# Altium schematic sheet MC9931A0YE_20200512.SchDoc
size A3
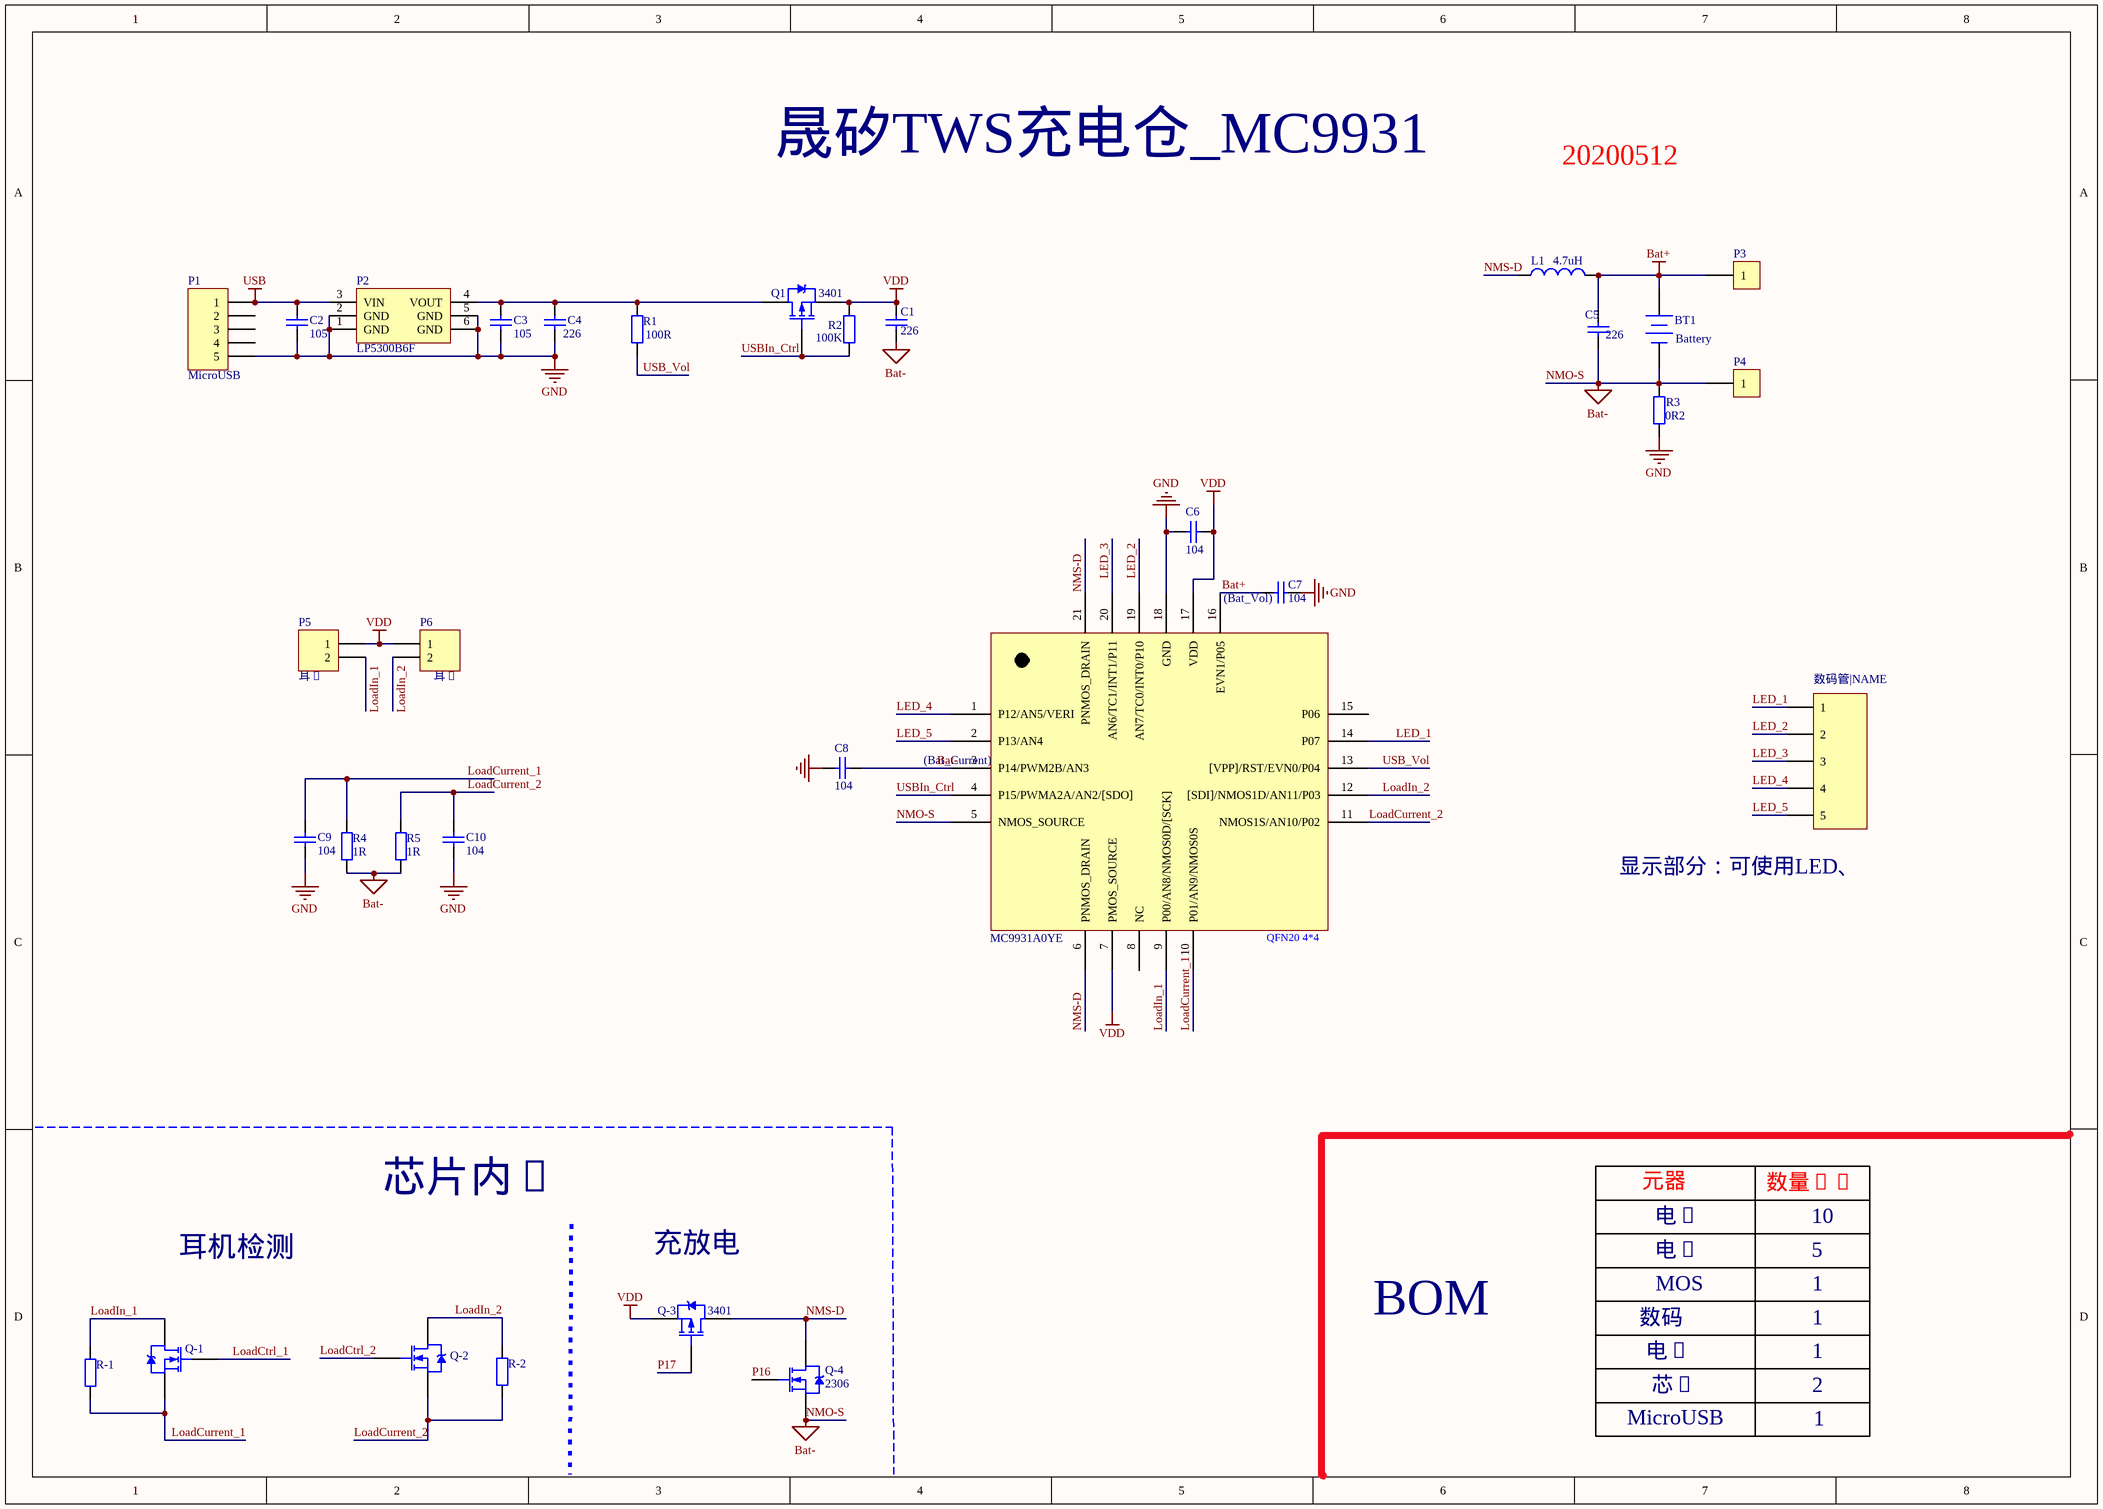
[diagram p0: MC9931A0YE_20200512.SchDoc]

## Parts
1  Header 5  [数码管_5脚]  (value not drawn)
BT1  Battery
C1  value 226  [0805]  (hidden comment: Cap)
C2  value 105  [0603]  (hidden comment: Cap)
C3  value 105  [0603]  (hidden comment: Cap)
C4  value 226  [0805]  (hidden comment: Cap)
C5  value 226  [0805]  (hidden comment: Cap)
C6  value 104  [0603]  (hidden comment: Cap)
C7  value 104  [0603]  (hidden comment: Cap)
C8  value 104  [0603]  (hidden comment: Cap)
C9  value 104  [0603]  (hidden comment: Cap)
C10  value 104  [0603]  (hidden comment: Cap)
L1  4.7uH  [电感SMD_201610]
MC1  MC9931A0YE  [QFN20_4*4 _Large]
P1  MicroUSB  [MICRO-USB_standard]
P2  LP5300B6F  [SOT23-6]
P3  Header 2  [1焊盘]  (value not drawn)
P4  Header 2  [1焊盘]  (value not drawn)
P5  Header 2  [1*2焊盘]  (value not drawn)
P6  Header 2  [1*2焊盘]  (value not drawn)
Q1  3401  [SOT-23_PMOS]
Q-1  3134  [TO-220AB]  (value not drawn)
Q-2  3134  [TO-220AB]  (value not drawn)
Q-3  3401  [SOT-23_PMOS]
Q-4  2306  [SOT-23_NMOS]
R1  value 100R  [0603]  (hidden comment: Res2)
R2  value 100K  [0603]  (hidden comment: Res2)
R3  value 0R2  [1206]  (hidden comment: Res2)
R4  value 1R  [0805]  (hidden comment: Res2)
R5  value 1R  [0805]  (hidden comment: Res2)
R-1  Res2  [AXIAL-0.4]  (value not drawn)
R-2  Res2  [AXIAL-0.4]  (value not drawn)

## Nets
Bat+: BT1.1(+) C5.2 C7.2 L1.2 MC1.16(EVN1/P05) P3.1
Bat-: BT1.2(-) C1.1 C5.1 C8.2 MC1.3(P14/PWM2B/AN3) MC1.5(NMOS_SOURCE) P4.1 Q-4.3(S) R3.2 R4.2 R5.2  [also labelled NMO-S]
GND: C2.1 C3.1 C4.1 C6.2 C7.1 C8.1 C9.2 C10.2 MC1.18(GND) P1.5 P2.1(GND) P2.2(GND) P2.5(GND) P2.6(GND) R3.1
USB: C2.2 P1.1 P2.3(VIN)
VDD: C1.2 C6.1 MC1.7(PMOS_SOURCE) MC1.17(VDD) P5.1 P6.1 Q1.3(S) Q-3.3(S) R2.1
LED_1: 1.1 MC1.14(P07)
LED_2: 1.2 MC1.19(AN7/TC0/INT0/P10)
LED_3: 1.3 MC1.20(AN6/TC1/INT1/P11)
LED_4: 1.4 MC1.1(P12/AN5/VERI)
LED_5: 1.5 MC1.2(P13/AN4)
LoadCtrl_1: Q-1.1(G)
LoadCtrl_2: Q-2.1(G)
LoadCurrent_1: C9.1 MC1.10(P01/AN9/NMOS0S) Q-1.3(S) R4.1 R-1.1
LoadCurrent_2: C10.1 MC1.11(NMOS1S/AN10/P02) Q-2.3(S) R5.1 R-2.1
LoadIn_1: MC1.9(P00/AN8/NMOS0D/[SCK]) P5.2 Q-1.2(D) R-1.2
LoadIn_2: MC1.12([SDI]/NMOS1D/AN11/P03) P6.2 Q-2.2(D) R-2.2
NMS-D: L1.1 MC1.6(PNMOS_DRAIN) MC1.21(PNMOS_DRAIN) Q-3.2(D) Q-4.2(D)
P16: Q-4.1(G)
P17: Q-3.1(G)
USB_Vol: MC1.13([VPP]/RST/EVN0/P04) R1.1
USBIn_Ctrl: MC1.4(P15/PWMA2A/AN2/[SDO]) Q1.1(G) R2.2
NetC3_2: C3.2 C4.2 P2.4(VOUT) Q1.2(D) R1.2

Not connected (* = marked no-connect by the designer): MC1 8(NC) 15(P06); P1 2 3 4

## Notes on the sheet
- 晟矽TWS充电仓_MC9931
- 20200512
- (near C7) (Bat_Vol)
- (near C8) (Bat_Current)
- 显示部分：可使用LED、
- (near MC1) QFN20 4*4
- 元器
- 数量(�
- 耳机检测
- 芯片内�
- 充放电
- 电�
- 10
- 5
- BOM
- 数码
- MOS
- 1
- 芯�
- 2
- MicroUSB

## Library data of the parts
1 P1 = Header 5: Header, 5-Pin
BT1 = Battery: Multicell Battery
C1-C10 = Cap: Capacitor
L1 = Inductor: Code_IEC: 1005; Value: 10mH
MC1 = MC9931A0ZQ
P2 = Header 3X2A: Header, 3-Pin, Dual row
P3-P6 = Header 2: Header, 2-Pin
Q1 Q-3 = PMOS-2: P-Channel Power MOSFET; Note: Pin 4 not drawn and electrically connected to Pin 2.
Q-1 Q-2 Q-4 = NMOS-2: N-Channel Power MOSFET; Note: Pin 2 is electrically connected to pin 4.
R1-R5 R-1 R-2 = Res2: Resistor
